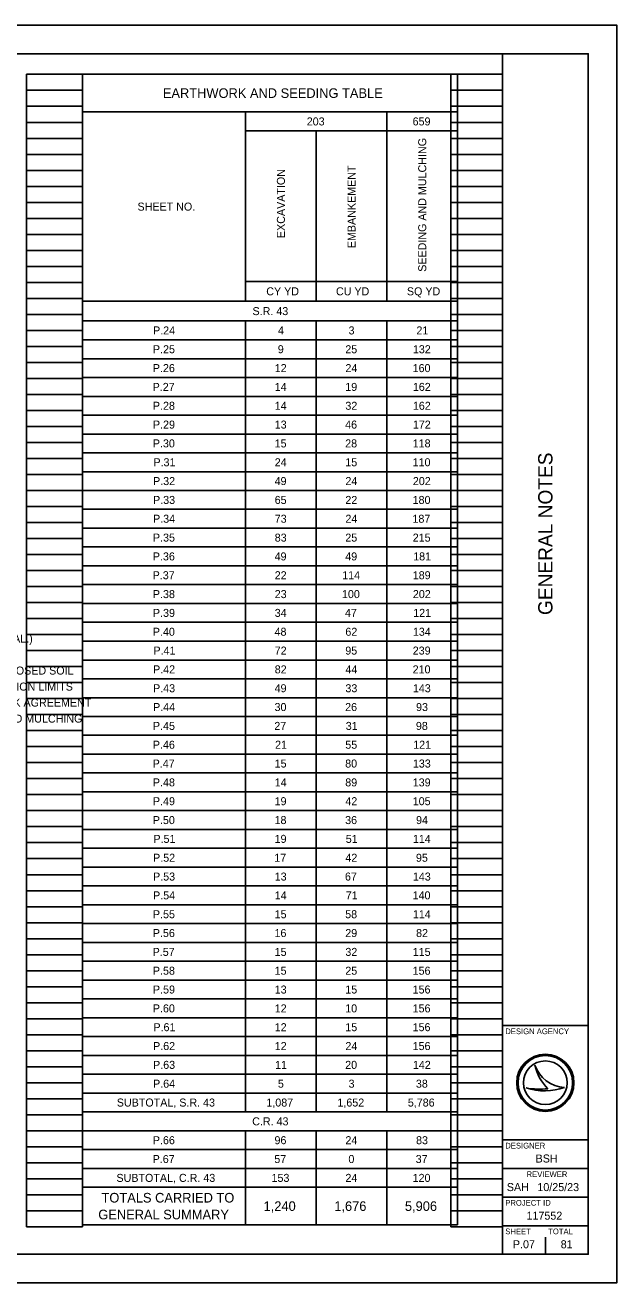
# Model space of a CAD drawing. Extents: x -9.3 to 90.7, y -9.7 to 44.8.
# Drawn here: x 23.66 to 34, y 0 to 22 of the extents above; entities that cross this region are included whole.
import ezdxf

# ---------------------------------------------------------------- set-up
doc = ezdxf.new("R2010")
doc.units = 0
for name, color, linetype in [('SH_Border', 7, 'Continuous'), ('SH_Cut_Line', 7, 'Continuous'), ('SH_Data', 7, 'Continuous'), ('SH_Text', 7, 'Continuous')]:
    doc.layers.add(name, color=color, linetype=linetype)

msp = doc.modelspace()

# ---------------------------------------------------------------- linework, layer by layer
at = {"layer": 'SH_Border'}
for p, q in [((32, 0.5), (32, 21.5)), ((32, 4.5), (33.5, 4.5)), ((32, 2.5), (33.5, 2.5)), ((32, 2), (33.5, 2)), ((32, 1.5), (33.5, 1.5)), ((32, 1), (33.5, 1))]:
    msp.add_line(p, q, dxfattribs=at)
msp.add_lwpolyline([(1.5, 21.5), (33.5, 21.5), (33.5, 0.5), (1.5, 0.5)], close=True, dxfattribs=at)
at = {"layer": 'SH_Cut_Line'}
msp.add_lwpolyline([(0, 0), (34, 0), (34, 22), (0, 22)], close=True, dxfattribs=at)
at = {"layer": 'SH_Data'}
for p, q in [((23.68, 0.98), (23.68, 21.14)), ((23.68, 21.14), (24.66, 21.14)), ((24.66, 0.98), (24.66, 21.14)), ((31.1, 0.98), (31.1, 21.14)), ((31.1, 21.14), (32, 21.14)), ((32, 0.98), (32, 21.14)), ((23.68, 20.86), (24.66, 20.86)), ((31.1, 20.86), (32, 20.86)), ((23.68, 20.58), (24.66, 20.58)), ((31.1, 20.58), (32, 20.58)), ((23.68, 20.3), (24.66, 20.3)), ((31.1, 20.3), (32, 20.3)), ((23.68, 20.02), (24.66, 20.02)), ((31.1, 20.02), (32, 20.02)), ((23.68, 19.74), (24.66, 19.74)), ((31.1, 19.74), (32, 19.74)), ((23.68, 19.46), (24.66, 19.46)), ((31.1, 19.46), (32, 19.46)), ((23.68, 19.18), (24.66, 19.18)), ((31.1, 19.18), (32, 19.18)), ((23.68, 18.9), (24.66, 18.9)), ((31.1, 18.9), (32, 18.9)), ((23.68, 18.62), (24.66, 18.62)), ((31.1, 18.62), (32, 18.62)), ((23.68, 18.34), (24.66, 18.34)), ((31.1, 18.34), (32, 18.34)), ((23.68, 18.06), (24.66, 18.06)), ((31.1, 18.06), (32, 18.06)), ((23.68, 17.78), (24.66, 17.78)), ((31.1, 17.78), (32, 17.78)), ((23.68, 17.5), (24.66, 17.5)), ((31.1, 17.5), (32, 17.5)), ((23.68, 17.22), (24.66, 17.22)), ((31.1, 17.22), (32, 17.22)), ((23.68, 16.94), (24.66, 16.94)), ((31.1, 16.94), (32, 16.94)), ((23.68, 16.66), (24.66, 16.66)), ((31.1, 16.66), (32, 16.66)), ((23.68, 16.38), (24.66, 16.38)), ((31.1, 16.38), (32, 16.38)), ((23.68, 16.1), (24.66, 16.1)), ((31.1, 16.1), (32, 16.1)), ((23.68, 15.82), (24.66, 15.82)), ((31.1, 15.82), (32, 15.82)), ((23.68, 15.54), (24.66, 15.54)), ((31.1, 15.54), (32, 15.54)), ((23.68, 15.26), (24.66, 15.26)), ((31.1, 15.26), (32, 15.26)), ((23.68, 14.98), (24.66, 14.98)), ((31.1, 14.98), (32, 14.98)), ((23.68, 14.7), (24.66, 14.7)), ((31.1, 14.7), (32, 14.7)), ((23.68, 14.42), (24.66, 14.42)), ((31.1, 14.42), (32, 14.42)), ((23.68, 14.14), (24.66, 14.14)), ((31.1, 14.14), (32, 14.14)), ((23.68, 13.86), (24.66, 13.86)), ((31.1, 13.86), (32, 13.86)), ((23.68, 13.58), (24.66, 13.58)), ((31.1, 13.58), (32, 13.58)), ((23.68, 13.3), (24.66, 13.3)), ((31.1, 13.3), (32, 13.3)), ((23.68, 13.02), (24.66, 13.02)), ((31.1, 13.02), (32, 13.02)), ((23.68, 12.74), (24.66, 12.74)), ((31.1, 12.74), (32, 12.74)), ((23.68, 12.46), (24.66, 12.46)), ((31.1, 12.46), (32, 12.46)), ((23.68, 12.18), (24.66, 12.18)), ((31.1, 12.18), (32, 12.18)), ((23.68, 11.9), (24.66, 11.9)), ((31.1, 11.9), (32, 11.9)), ((23.68, 11.62), (24.66, 11.62)), ((31.1, 11.62), (32, 11.62)), ((23.68, 11.34), (24.66, 11.34)), ((31.1, 11.34), (32, 11.34)), ((23.68, 11.06), (24.66, 11.06)), ((31.1, 11.06), (32, 11.06)), ((23.68, 10.78), (24.66, 10.78)), ((31.1, 10.78), (32, 10.78)), ((23.68, 10.5), (24.66, 10.5)), ((31.1, 10.5), (32, 10.5)), ((23.68, 10.22), (24.66, 10.22)), ((31.1, 10.22), (32, 10.22)), ((23.68, 9.94), (24.66, 9.94)), ((31.1, 9.94), (32, 9.94)), ((23.68, 9.66), (24.66, 9.66)), ((31.1, 9.66), (32, 9.66)), ((23.68, 9.38), (24.66, 9.38)), ((31.1, 9.38), (32, 9.38)), ((23.68, 9.1), (24.66, 9.1)), ((31.1, 9.1), (32, 9.1)), ((23.68, 8.82), (24.66, 8.82)), ((31.1, 8.82), (32, 8.82)), ((23.68, 8.54), (24.66, 8.54)), ((31.1, 8.54), (32, 8.54)), ((23.68, 8.26), (24.66, 8.26)), ((31.1, 8.26), (32, 8.26)), ((23.68, 7.98), (24.66, 7.98)), ((31.1, 7.98), (32, 7.98)), ((23.68, 7.7), (24.66, 7.7)), ((31.1, 7.7), (32, 7.7)), ((23.68, 7.42), (24.66, 7.42)), ((31.1, 7.42), (32, 7.42)), ((23.68, 7.14), (24.66, 7.14)), ((31.1, 7.14), (32, 7.14)), ((23.68, 6.86), (24.66, 6.86)), ((31.1, 6.86), (32, 6.86)), ((23.68, 6.58), (24.66, 6.58)), ((31.1, 6.58), (32, 6.58)), ((23.68, 6.3), (24.66, 6.3)), ((31.1, 6.3), (32, 6.3)), ((23.68, 6.02), (24.66, 6.02)), ((31.1, 6.02), (32, 6.02)), ((23.68, 5.74), (24.66, 5.74)), ((31.1, 5.74), (32, 5.74)), ((23.68, 5.46), (24.66, 5.46)), ((31.1, 5.46), (32, 5.46)), ((23.68, 5.18), (24.66, 5.18)), ((31.1, 5.18), (32, 5.18)), ((23.68, 4.9), (24.66, 4.9)), ((31.1, 4.9), (32, 4.9)), ((23.68, 4.62), (24.66, 4.62)), ((31.1, 4.62), (32, 4.62)), ((23.68, 4.34), (24.66, 4.34)), ((31.1, 4.34), (32, 4.34)), ((23.68, 4.06), (24.66, 4.06)), ((31.1, 4.06), (32, 4.06)), ((23.68, 3.78), (24.66, 3.78)), ((31.1, 3.78), (32, 3.78)), ((32.567, 3.81), (32.567, 3.81)), ((23.68, 3.5), (24.66, 3.5)), ((31.1, 3.5), (32, 3.5)), ((32.417, 3.41), (32.417, 3.41)), ((32.75, 3.5), (32.75, 3.5)), ((33.087, 3.419), (33.087, 3.419)), ((23.68, 3.22), (24.66, 3.22)), ((31.1, 3.22), (32, 3.22)), ((23.68, 2.94), (24.66, 2.94)), ((31.1, 2.94), (32, 2.94)), ((23.68, 2.66), (24.66, 2.66)), ((31.1, 2.66), (32, 2.66)), ((23.68, 2.38), (24.66, 2.38)), ((31.1, 2.38), (32, 2.38)), ((23.68, 2.1), (24.66, 2.1)), ((31.1, 2.1), (32, 2.1)), ((23.68, 1.82), (24.66, 1.82)), ((31.1, 1.82), (32, 1.82)), ((23.68, 1.54), (24.66, 1.54)), ((31.1, 1.54), (32, 1.54)), ((23.68, 1.26), (24.66, 1.26)), ((31.1, 1.26), (32, 1.26)), ((23.68, 0.98), (24.66, 0.98)), ((31.1, 0.98), (32, 0.98)), ((32.375, 0.675), (32.375, 0.675)), ((32.75, 0.5), (32.75, 0.8))]:
    msp.add_line(p, q, dxfattribs=at)
for radius in [0.5, 0.477, 0.477, 0.382]:
    msp.add_circle((32.75, 3.5), radius, dxfattribs=at)
for centre, radius, start, end in [((33.116, 3.998), 0.58, 198.9257, 198.9319), ((33.347, 3.97), 0.796, 191.6379, 191.6421), ((33.116, 3.998), 0.58, 198.9319, 267.1657), ((33.347, 3.97), 0.796, 191.6421, 226.0947), ((32.739, 4.37), 1.013, 251.4576, 290.0832), ((32.648, 4.654), 1.266, 259.4964, 259.4995), ((32.739, 4.37), 1.013, 251.4527, 251.4576), ((32.648, 4.654), 1.266, 259.4995, 276.6672)]:
    msp.add_arc(centre, radius, start, end, dxfattribs=at)
at = {"layer": 'SH_Text'}
for p, q in [((24.66, 21.14), (31.215, 21.14)), ((24.66, 21.14), (24.66, 1.013)), ((31.215, 21.14), (31.215, 1.013)), ((24.66, 20.481), (31.215, 20.481)), ((27.509, 20.481), (27.509, 17.171)), ((29.98, 20.481), (29.98, 17.171)), ((27.509, 20.152), (31.215, 20.152)), ((28.745, 20.152), (28.745, 17.171)), ((27.509, 17.516), (31.215, 17.516)), ((24.66, 17.171), (31.215, 17.171)), ((24.66, 16.825), (31.215, 16.825)), ((27.509, 16.825), (27.509, 2.989)), ((28.745, 16.825), (28.745, 2.989)), ((29.98, 16.825), (29.98, 2.989)), ((24.66, 16.495), (31.215, 16.495)), ((24.66, 16.166), (31.215, 16.166)), ((24.66, 15.836), (31.215, 15.836)), ((24.66, 15.507), (31.215, 15.507)), ((24.66, 15.178), (31.215, 15.178)), ((24.66, 14.848), (31.215, 14.848)), ((24.66, 14.519), (31.215, 14.519)), ((24.66, 14.189), (31.215, 14.189)), ((24.66, 13.86), (31.215, 13.86)), ((24.66, 13.531), (31.215, 13.531)), ((24.66, 13.201), (31.215, 13.201)), ((24.66, 12.872), (31.215, 12.872)), ((24.66, 12.542), (31.215, 12.542)), ((24.66, 12.213), (31.215, 12.213)), ((24.66, 11.884), (31.215, 11.884)), ((24.66, 11.554), (31.215, 11.554)), ((24.66, 11.225), (31.215, 11.225)), ((24.66, 10.895), (31.215, 10.895)), ((24.66, 10.566), (31.215, 10.566)), ((24.66, 10.236), (31.215, 10.236)), ((24.66, 9.907), (31.215, 9.907)), ((24.66, 9.578), (31.215, 9.578)), ((24.66, 9.248), (31.215, 9.248)), ((24.66, 8.919), (31.215, 8.919)), ((24.66, 8.589), (31.215, 8.589)), ((24.66, 8.26), (31.215, 8.26)), ((24.66, 7.931), (31.215, 7.931)), ((24.66, 7.601), (31.215, 7.601)), ((24.66, 7.272), (31.215, 7.272)), ((24.66, 6.942), (31.215, 6.942)), ((24.66, 6.613), (31.215, 6.613)), ((24.66, 6.284), (31.215, 6.284)), ((24.66, 5.954), (31.215, 5.954)), ((24.66, 5.625), (31.215, 5.625)), ((24.66, 5.295), (31.215, 5.295)), ((24.66, 4.966), (31.215, 4.966)), ((24.66, 4.636), (31.215, 4.636)), ((24.66, 4.307), (31.215, 4.307)), ((24.66, 3.978), (31.215, 3.978)), ((24.66, 3.648), (31.215, 3.648)), ((24.66, 3.319), (31.215, 3.319)), ((24.66, 2.989), (31.215, 2.989)), ((24.66, 2.66), (31.215, 2.66)), ((27.509, 2.66), (27.509, 1.672)), ((28.745, 2.66), (28.745, 1.672)), ((29.98, 2.66), (29.98, 1.672)), ((24.66, 2.331), (31.215, 2.331)), ((24.66, 2.001), (31.215, 2.001)), ((24.66, 1.672), (31.215, 1.672)), ((27.509, 1.672), (27.509, 1.013)), ((28.745, 1.672), (28.745, 1.013)), ((29.98, 1.672), (29.98, 1.013)), ((24.66, 1.013), (31.215, 1.013))]:
    msp.add_line(p, q, dxfattribs=at)

# ---------------------------------------------------------------- texts
at = {"layer": 'SH_Data'}
msp.add_text('GENERAL NOTES', height=0.25, rotation=90, dxfattribs=at).set_placement((32.875, 11.682))
for s, height, p in [('(USE 35 M. GAL.)', 0.14, (22.28, 11.2)), ('DESIGN AGENCY', 0.1, (32.05, 4.35)), ('DESIGNER', 0.1, (32.05, 2.35)), ('BSH', 0.14, (32.58, 2.105)), ('REVIEWER', 0.1, (32.422, 1.85)), ('SAH', 0.14, (32.077, 1.605)), ('10/25/23', 0.14, (32.611, 1.605)), ('PROJECT ID', 0.1, (32.05, 1.35)), ('117552', 0.14, (32.421, 1.105)), ('SHEET', 0.1, (32.05, 0.85)), ('TOTAL', 0.1, (32.8, 0.85)), ('P.07', 0.14, (32.183, 0.605)), ('81', 0.14, (33.019, 0.605))]:
    msp.add_text(s, height=height, dxfattribs=at).set_placement(p)
at = {"layer": 'SH_Text'}
for s, height, p in [('EARTHWORK AND SEEDING TABLE', 0.168, (26.063, 20.727)), ('203', 0.14, (28.579, 20.246)), ('659', 0.14, (30.43, 20.246)), ('SHEET NO.', 0.14, (25.62, 18.756)), ('CY YD', 0.14, (27.871, 17.274)), ('CU YD', 0.14, (29.09, 17.274)), ('SQ YD', 0.14, (30.33, 17.274)), ('S.R. 43', 0.14, (27.631, 16.928)), ('P.24', 0.14, (25.892, 16.59)), ('4', 0.14, (28.075, 16.59)), ('3', 0.14, (29.31, 16.59)), ('21', 0.14, (30.496, 16.59)), ('P.25', 0.14, (25.89, 16.261)), ('9', 0.14, (28.073, 16.261)), ('25', 0.14, (29.253, 16.261)), ('132', 0.14, (30.434, 16.261)), ('P.26', 0.14, (25.888, 15.931)), ('12', 0.14, (28.019, 15.931)), ('24', 0.14, (29.255, 15.931)), ('160', 0.14, (30.43, 15.931)), ('P.27', 0.14, (25.885, 15.602)), ('14', 0.14, (28.019, 15.602)), ('19', 0.14, (29.252, 15.602)), ('162', 0.14, (30.434, 15.602)), ('P.28', 0.14, (25.889, 15.272)), ('14', 0.14, (28.019, 15.272)), ('32', 0.14, (29.254, 15.272)), ('162', 0.14, (30.434, 15.272)), ('P.29', 0.14, (25.89, 14.943)), ('13', 0.14, (28.019, 14.943)), ('46', 0.14, (29.25, 14.943)), ('172', 0.14, (30.434, 14.943)), ('P.30', 0.14, (25.888, 14.614)), ('15', 0.14, (28.018, 14.614)), ('28', 0.14, (29.251, 14.614)), ('118', 0.14, (30.431, 14.614)), ('P.31', 0.14, (25.898, 14.284)), ('24', 0.14, (28.019, 14.284)), ('15', 0.14, (29.253, 14.284)), ('110', 0.14, (30.43, 14.284)), ('P.32', 0.14, (25.892, 13.955)), ('49', 0.14, (28.017, 13.955)), ('24', 0.14, (29.255, 13.955)), ('202', 0.14, (30.434, 13.955)), ('P.33', 0.14, (25.892, 13.625)), ('65', 0.14, (28.018, 13.625)), ('22', 0.14, (29.254, 13.625)), ('180', 0.14, (30.43, 13.625)), ('P.34', 0.14, (25.892, 13.296)), ('73', 0.14, (28.019, 13.296)), ('24', 0.14, (29.255, 13.296)), ('187', 0.14, (30.427, 13.296)), ('P.35', 0.14, (25.89, 12.966)), ('83', 0.14, (28.019, 12.966)), ('25', 0.14, (29.253, 12.966)), ('215', 0.14, (30.432, 12.966)), ('P.36', 0.14, (25.888, 12.637)), ('49', 0.14, (28.017, 12.637)), ('49', 0.14, (29.252, 12.637)), ('181', 0.14, (30.44, 12.637)), ('P.37', 0.14, (25.885, 12.308)), ('22', 0.14, (28.019, 12.308)), ('114', 0.14, (29.199, 12.308)), ('189', 0.14, (30.432, 12.308)), ('P.38', 0.14, (25.889, 11.978)), ('23', 0.14, (28.019, 11.978)), ('100', 0.14, (29.195, 11.978)), ('202', 0.14, (30.434, 11.978)), ('P.39', 0.14, (25.89, 11.649)), ('34', 0.14, (28.019, 11.649)), ('47', 0.14, (29.247, 11.649)), ('121', 0.14, (30.44, 11.649)), ('P.40', 0.14, (25.888, 11.319)), ('48', 0.14, (28.016, 11.319)), ('62', 0.14, (29.254, 11.319)), ('134', 0.14, (30.434, 11.319)), ('P.41', 0.14, (25.898, 10.99)), ('72', 0.14, (28.019, 10.99)), ('95', 0.14, (29.253, 10.99)), ('239', 0.14, (30.432, 10.99)), ('SEEDING AND MULCHING SHALL BE APPLIED TO ALL AREAS OF EXPOSED SOIL ', 0.14, (17.24, 10.64)), ('P.42', 0.14, (25.892, 10.661)), ('82', 0.14, (28.019, 10.661)), ('44', 0.14, (29.255, 10.661)), ('210', 0.14, (30.43, 10.661)), ('BETWEEN THE RIGHT-OF-WAY LINES, AND WITHIN THE CONSTRUCTION LIMITS ', 0.14, (17.24, 10.36)), ('P.43', 0.14, (25.892, 10.331)), ('49', 0.14, (28.017, 10.331)), ('33', 0.14, (29.255, 10.331)), ('143', 0.14, (30.434, 10.331)), ('FOR AREAS OUTSIDE THE RIGHT-OF WAY LINES COVERED BY WORK AGREEMENT ', 0.14, (17.24, 10.08)), ('P.44', 0.14, (25.892, 10.002)), ('30', 0.14, (28.016, 10.002)), ('26', 0.14, (29.25, 10.002)), ('93', 0.14, (30.49, 10.002)), ('OR SLOPE EASEMENT. QUANTITY CALCULATIONS FOR SEEDING AND MULCHING ', 0.14, (17.24, 9.8)), ('P.45', 0.14, (25.89, 9.672)), ('27', 0.14, (28.012, 9.672)), ('31', 0.14, (29.261, 9.672)), ('98', 0.14, (30.487, 9.672)), ('P.46', 0.14, (25.888, 9.343)), ('21', 0.14, (28.025, 9.343)), ('55', 0.14, (29.253, 9.343)), ('121', 0.14, (30.44, 9.343)), ('P.47', 0.14, (25.885, 9.014)), ('15', 0.14, (28.018, 9.014)), ('80', 0.14, (29.251, 9.014)), ('133', 0.14, (30.434, 9.014)), ('P.48', 0.14, (25.889, 8.684)), ('14', 0.14, (28.019, 8.684)), ('89', 0.14, (29.252, 8.684)), ('139', 0.14, (30.432, 8.684)), ('P.49', 0.14, (25.89, 8.355)), ('19', 0.14, (28.017, 8.355)), ('42', 0.14, (29.254, 8.355)), ('105', 0.14, (30.432, 8.355)), ('P.50', 0.14, (25.888, 8.025)), ('18', 0.14, (28.016, 8.025)), ('36', 0.14, (29.25, 8.025)), ('94', 0.14, (30.49, 8.025)), ('P.51', 0.14, (25.898, 7.696)), ('19', 0.14, (28.017, 7.696)), ('51', 0.14, (29.261, 7.696)), ('114', 0.14, (30.434, 7.696)), ('P.52', 0.14, (25.892, 7.366)), ('17', 0.14, (28.012, 7.366)), ('42', 0.14, (29.254, 7.366)), ('95', 0.14, (30.488, 7.366)), ('P.53', 0.14, (25.892, 7.037)), ('13', 0.14, (28.019, 7.037)), ('67', 0.14, (29.247, 7.037)), ('143', 0.14, (30.434, 7.037)), ('P.54', 0.14, (25.892, 6.708)), ('14', 0.14, (28.019, 6.708)), ('71', 0.14, (29.261, 6.708)), ('140', 0.14, (30.43, 6.708)), ('P.55', 0.14, (25.89, 6.378)), ('15', 0.14, (28.018, 6.378)), ('58', 0.14, (29.251, 6.378)), ('114', 0.14, (30.434, 6.378)), ('P.56', 0.14, (25.888, 6.049)), ('16', 0.14, (28.015, 6.049)), ('29', 0.14, (29.252, 6.049)), ('82', 0.14, (30.49, 6.049)), ('P.57', 0.14, (25.885, 5.719)), ('15', 0.14, (28.018, 5.719)), ('32', 0.14, (29.254, 5.719)), ('115', 0.14, (30.432, 5.719)), ('P.58', 0.14, (25.889, 5.39)), ('15', 0.14, (28.018, 5.39)), ('25', 0.14, (29.253, 5.39)), ('156', 0.14, (30.43, 5.39)), ('P.59', 0.14, (25.89, 5.061)), ('13', 0.14, (28.019, 5.061)), ('15', 0.14, (29.253, 5.061)), ('156', 0.14, (30.43, 5.061)), ('P.60', 0.14, (25.888, 4.731)), ('12', 0.14, (28.019, 4.731)), ('10', 0.14, (29.251, 4.731)), ('156', 0.14, (30.43, 4.731)), ('P.61', 0.14, (25.898, 4.402)), ('12', 0.14, (28.019, 4.402)), ('15', 0.14, (29.253, 4.402)), ('156', 0.14, (30.43, 4.402)), ('P.62', 0.14, (25.892, 4.072)), ('12', 0.14, (28.019, 4.072)), ('24', 0.14, (29.255, 4.072)), ('156', 0.14, (30.43, 4.072)), ('P.63', 0.14, (25.892, 3.743)), ('11', 0.14, (28.025, 3.743)), ('20', 0.14, (29.251, 3.743)), ('142', 0.14, (30.434, 3.743)), ('P.64', 0.14, (25.892, 3.414)), ('5', 0.14, (28.074, 3.414)), ('3', 0.14, (29.31, 3.414)), ('38', 0.14, (30.487, 3.414)), ('SUBTOTAL, S.R. 43', 0.14, (25.258, 3.084)), ('1,087', 0.14, (27.873, 3.084)), ('1,652', 0.14, (29.115, 3.084)), ('5,786', 0.14, (30.346, 3.084)), ('C.R. 43', 0.14, (27.625, 2.755)), ('P.66', 0.14, (25.888, 2.425)), ('96', 0.14, (28.015, 2.425)), ('24', 0.14, (29.255, 2.425)), ('83', 0.14, (30.49, 2.425)), ('P.67', 0.14, (25.885, 2.096)), ('57', 0.14, (28.012, 2.096)), ('0', 0.14, (29.307, 2.096)), ('37', 0.14, (30.483, 2.096)), ('SUBTOTAL, C.R. 43', 0.14, (25.252, 1.766)), ('153', 0.14, (27.963, 1.766)), ('24', 0.14, (29.255, 1.766)), ('120', 0.14, (30.43, 1.766)), ('TOTALS CARRIED TO ', 0.168, (24.991, 1.405)), ('1,240', 0.168, (27.824, 1.258)), ('1,676', 0.168, (29.06, 1.258)), ('5,906', 0.168, (30.295, 1.258)), ('GENERAL SUMMARY', 0.168, (24.934, 1.111))]:
    msp.add_text(s, height=height, dxfattribs=at).set_placement(p)
for s, p in [('SEEDING AND MULCHING', (30.668, 17.686)), ('EXCAVATION', (28.197, 18.276)), ('EMBANKEMENT', (29.432, 18.1))]:
    msp.add_text(s, height=0.14, rotation=90, dxfattribs=at).set_placement(p)

doc.saveas('drawing.dxf')
